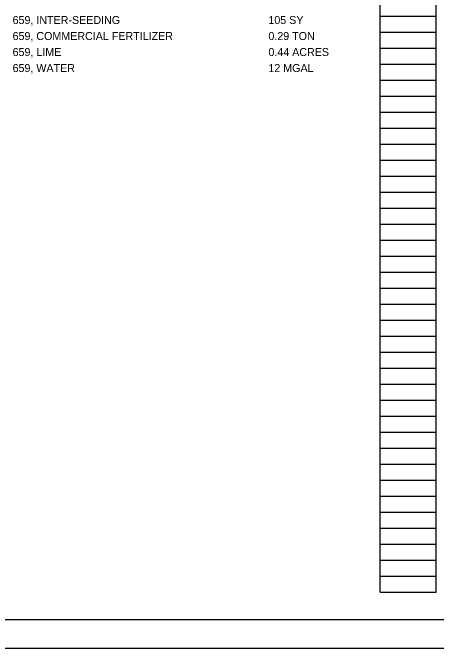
# Model space of a CAD drawing. Extents: x -19 to 64.6, y -1.7 to 22.
# Drawn here: x 17.24 to 24.66, y 0 to 11.12 of the extents above; entities that cross this region are included whole.
import ezdxf

# ---------------------------------------------------------------- set-up
doc = ezdxf.new("R2010")
doc.units = 0
for name, color, linetype in [('SH_Border', 7, 'Continuous'), ('SH_Cut_Line', 7, 'Continuous'), ('SH_Data', 7, 'Continuous'), ('SH_Text', 7, 'Continuous')]:
    doc.layers.add(name, color=color, linetype=linetype)

msp = doc.modelspace()

# ---------------------------------------------------------------- linework, layer by layer
at = {"layer": 'SH_Border'}
msp.add_lwpolyline([(1.5, 21.5), (33.5, 21.5), (33.5, 0.5), (1.5, 0.5)], close=True, dxfattribs=at)
at = {"layer": 'SH_Cut_Line'}
msp.add_lwpolyline([(0, 0), (34, 0), (34, 22), (0, 22)], close=True, dxfattribs=at)
at = {"layer": 'SH_Data'}
for p, q in [((23.68, 0.98), (23.68, 21.14)), ((24.66, 0.98), (24.66, 21.14)), ((23.68, 11.06), (24.66, 11.06)), ((23.68, 10.78), (24.66, 10.78)), ((23.68, 10.5), (24.66, 10.5)), ((23.68, 10.22), (24.66, 10.22)), ((23.68, 9.94), (24.66, 9.94)), ((23.68, 9.66), (24.66, 9.66)), ((23.68, 9.38), (24.66, 9.38)), ((23.68, 9.1), (24.66, 9.1)), ((23.68, 8.82), (24.66, 8.82)), ((23.68, 8.54), (24.66, 8.54)), ((23.68, 8.26), (24.66, 8.26)), ((23.68, 7.98), (24.66, 7.98)), ((23.68, 7.7), (24.66, 7.7)), ((23.68, 7.42), (24.66, 7.42)), ((23.68, 7.14), (24.66, 7.14)), ((23.68, 6.86), (24.66, 6.86)), ((23.68, 6.58), (24.66, 6.58)), ((23.68, 6.3), (24.66, 6.3)), ((23.68, 6.02), (24.66, 6.02)), ((23.68, 5.74), (24.66, 5.74)), ((23.68, 5.46), (24.66, 5.46)), ((23.68, 5.18), (24.66, 5.18)), ((23.68, 4.9), (24.66, 4.9)), ((23.68, 4.62), (24.66, 4.62)), ((23.68, 4.34), (24.66, 4.34)), ((23.68, 4.06), (24.66, 4.06)), ((23.68, 3.78), (24.66, 3.78)), ((23.68, 3.5), (24.66, 3.5)), ((23.68, 3.22), (24.66, 3.22)), ((23.68, 2.94), (24.66, 2.94)), ((23.68, 2.66), (24.66, 2.66)), ((23.68, 2.38), (24.66, 2.38)), ((23.68, 2.1), (24.66, 2.1)), ((23.68, 1.82), (24.66, 1.82)), ((23.68, 1.54), (24.66, 1.54)), ((23.68, 1.26), (24.66, 1.26)), ((23.68, 0.98), (24.66, 0.98))]:
    msp.add_line(p, q, dxfattribs=at)

# ---------------------------------------------------------------- texts
at = {"layer": 'SH_Text'}
for s, p in [('659, INTER-SEEDING                 ', (17.24, 10.92)), ('105 SY', (21.72, 10.92)), ('659, COMMERCIAL FERTILIZER         ', (17.24, 10.64)), ('0.29 TON', (21.72, 10.64)), ('659, LIME                          ', (17.24, 10.36)), ('0.44 ACRES', (21.72, 10.36)), ('659, WATER                         ', (17.24, 10.08)), ('12 MGAL', (21.72, 10.08))]:
    msp.add_text(s, height=0.14, dxfattribs=at).set_placement(p)

doc.saveas('drawing.dxf')
